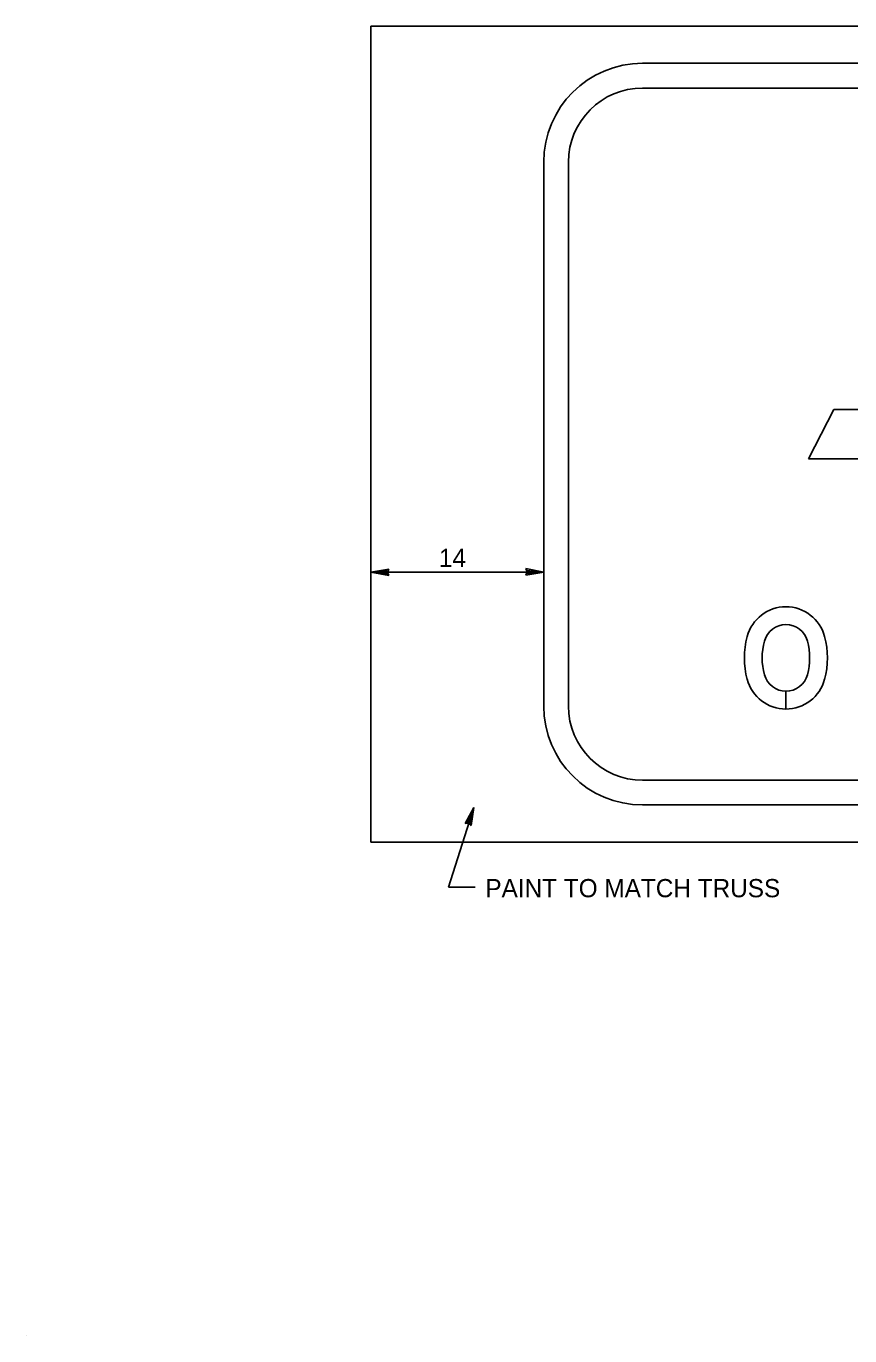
# Model space of a CAD drawing. Extents: x 60714 to 61340, y 9359 to 9750.
# Drawn here: x 60713.6 to 60840.2, y 9359 to 9560.3 of the extents above; entities that cross this region are included whole.
import ezdxf

# ---------------------------------------------------------------- set-up
doc = ezdxf.new("R2010")
doc.units = 0
for name, color, linetype in [('1', 7, 'Continuous'), ('2', 7, 'Continuous'), ('52', 7, 'Continuous'), ('AdhocPoint_dp', 7, 'Continuous'), ('GSBWFill', 7, 'Continuous'), ('SignPanel', 7, 'Continuous')]:
    doc.layers.add(name, color=color, linetype=linetype)

msp = doc.modelspace()

# ---------------------------------------------------------------- linework, layer by layer
at = {"layer": '1'}
for p, q in [((60766.57, 9476.35), (60793.17, 9476.35)), ((60778.52, 9427.94), (60782.43, 9440.19)), ((60778.52, 9427.94), (60782.63, 9427.92))]:
    msp.add_line(p, q, dxfattribs=at)
at = {"layer": '2'}
for p, q in [((60766.57, 9434.87), (60766.57, 9560.27)), ((60766.57, 9560.27), (61093.37, 9560.27)), ((60766.57, 9434.87), (61093.37, 9434.87))]:
    msp.add_line(p, q, dxfattribs=at)
at = {"layer": '52'}
for p, q in [((60766.57, 9476.35), (60769.35, 9476.8)), ((60766.57, 9476.35), (60769.23, 9476.54)), ((60766.57, 9476.35), (60769.33, 9475.82)), ((60766.57, 9476.35), (60769.22, 9476.08)), ((60769.13, 9476.31), (60769.35, 9476.8)), ((60769.33, 9475.82), (60769.13, 9476.31)), ((60790.61, 9476.4), (60790.39, 9475.91)), ((60793.17, 9476.35), (60790.39, 9475.91)), ((60793.17, 9476.35), (60790.41, 9476.89)), ((60790.41, 9476.89), (60790.61, 9476.4)), ((60793.17, 9476.35), (60790.51, 9476.63)), ((60793.17, 9476.35), (60790.51, 9476.17)), ((60782.43, 9440.19), (60781.08, 9437.72)), ((60782.43, 9440.19), (60781.35, 9437.74)), ((60782.43, 9440.19), (60781.79, 9437.6)), ((60782.43, 9440.19), (60782, 9437.41)), ((60781.08, 9437.72), (60781.61, 9437.77)), ((60781.61, 9437.77), (60782, 9437.41))]:
    msp.add_line(p, q, dxfattribs=at)
at = {"layer": 'AdhocPoint_dp'}
msp.add_line((60713.58, 9358.97), (60713.58, 9358.97), dxfattribs=at)
at = {"layer": 'GSBWFill'}
for p, q in [((60830.41, 9455.3), (60830.41, 9458.04)), ((60830.41, 9458.04), (60830.41, 9455.3)), ((60830.41, 9455.3), (60830.41, 9458.04)), ((60830.41, 9458.04), (60830.41, 9455.3))]:
    msp.add_line(p, q, dxfattribs=at)
for centre, radius, start, end in [((60830.41, 9464.88), 6.16, 14.9618, 165.0382), ((60830.41, 9464.88), 6.16, 14.9618, 165.0382), ((60830.41, 9464.88), 6.16, 14.9618, 165.0382), ((60830.41, 9464.88), 3.42, 14.9618, 165.0382), ((60830.41, 9464.88), 3.42, 14.9618, 165.0382), ((60830.41, 9464.88), 3.42, 14.9618, 165.0382), ((60836.79, 9463.17), 12.77, 165.0382, 194.9618), ((60836.79, 9463.17), 12.77, 165.0382, 194.9618), ((60836.79, 9463.17), 12.77, 165.0382, 194.9618), ((60836.79, 9463.17), 10.03, 165.0382, 194.9618), ((60836.79, 9463.17), 10.03, 165.0382, 194.9618), ((60836.79, 9463.17), 10.03, 165.0382, 194.9618), ((60824.02, 9463.17), 10.03, 345.0382, 14.9618), ((60824.02, 9463.17), 10.03, 345.0382, 14.9618), ((60824.02, 9463.17), 10.03, 345.0382, 14.9618), ((60824.02, 9463.17), 12.77, 345.0382, 14.9618), ((60824.02, 9463.17), 12.77, 345.0382, 14.9618), ((60824.02, 9463.17), 12.77, 345.0382, 14.9618), ((60830.41, 9461.47), 6.16, 194.9618, 345.0382), ((60830.41, 9461.47), 6.16, 194.9618, 270), ((60830.41, 9461.47), 6.16, 194.9618, 270), ((60830.41, 9461.47), 3.42, 194.9618, 345.0382), ((60830.41, 9461.47), 3.42, 194.9618, 270), ((60830.41, 9461.47), 3.42, 194.9618, 270), ((60830.41, 9461.47), 3.42, 270.0127, 345.0382), ((60830.41, 9461.47), 3.42, 270.0127, 345.0382), ((60830.41, 9461.47), 6.16, 270.0071, 345.0382), ((60830.41, 9461.47), 6.16, 270.0071, 345.0382)]:
    msp.add_arc(centre, radius, start, end, dxfattribs=at)
at = {"layer": 'SignPanel'}
for p, q in [((60808.37, 9554.57), (61051.57, 9554.57)), ((60808.37, 9550.77), (61051.57, 9550.77)), ((60793.17, 9455.77), (60793.17, 9539.37)), ((60796.97, 9455.77), (60796.97, 9539.37)), ((60837.77, 9501.37), (60833.9, 9493.77)), ((60837.77, 9501.37), (60861.19, 9501.37)), ((60833.9, 9493.77), (60864.93, 9493.77)), ((60808.37, 9444.37), (61051.57, 9444.37)), ((60808.37, 9440.57), (61051.57, 9440.57))]:
    msp.add_line(p, q, dxfattribs=at)
for centre, radius, start, end in [((60808.37, 9539.37), 15.2, 90, 180), ((60808.37, 9539.37), 11.4, 90, 180), ((60808.37, 9455.77), 15.2, 180, 270), ((60808.37, 9455.77), 11.4, 180, 270)]:
    msp.add_arc(centre, radius, start, end, dxfattribs=at)

# ---------------------------------------------------------------- texts
at = {"layer": '1'}
for s, p in [('14', (60777.04, 9477.14)), ('PAINT TO MATCH TRUSS', (60784.19, 9426.38))]:
    msp.add_text(s, height=2.8, rotation=0, dxfattribs=at).set_placement(p)

doc.saveas('drawing.dxf')
